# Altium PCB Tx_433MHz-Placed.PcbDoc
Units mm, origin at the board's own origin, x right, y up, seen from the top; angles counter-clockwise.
Board outline 100 x 50 mm, 4 copper layers (SIGNAL_1, SIGNAL_2, SIGNAL_3, SIGNAL_4), stack 1.58 mm thick; 34 components, 24 nets, 121 pads, 0 vias.
Unrouted connection lines stored in the file: 90.
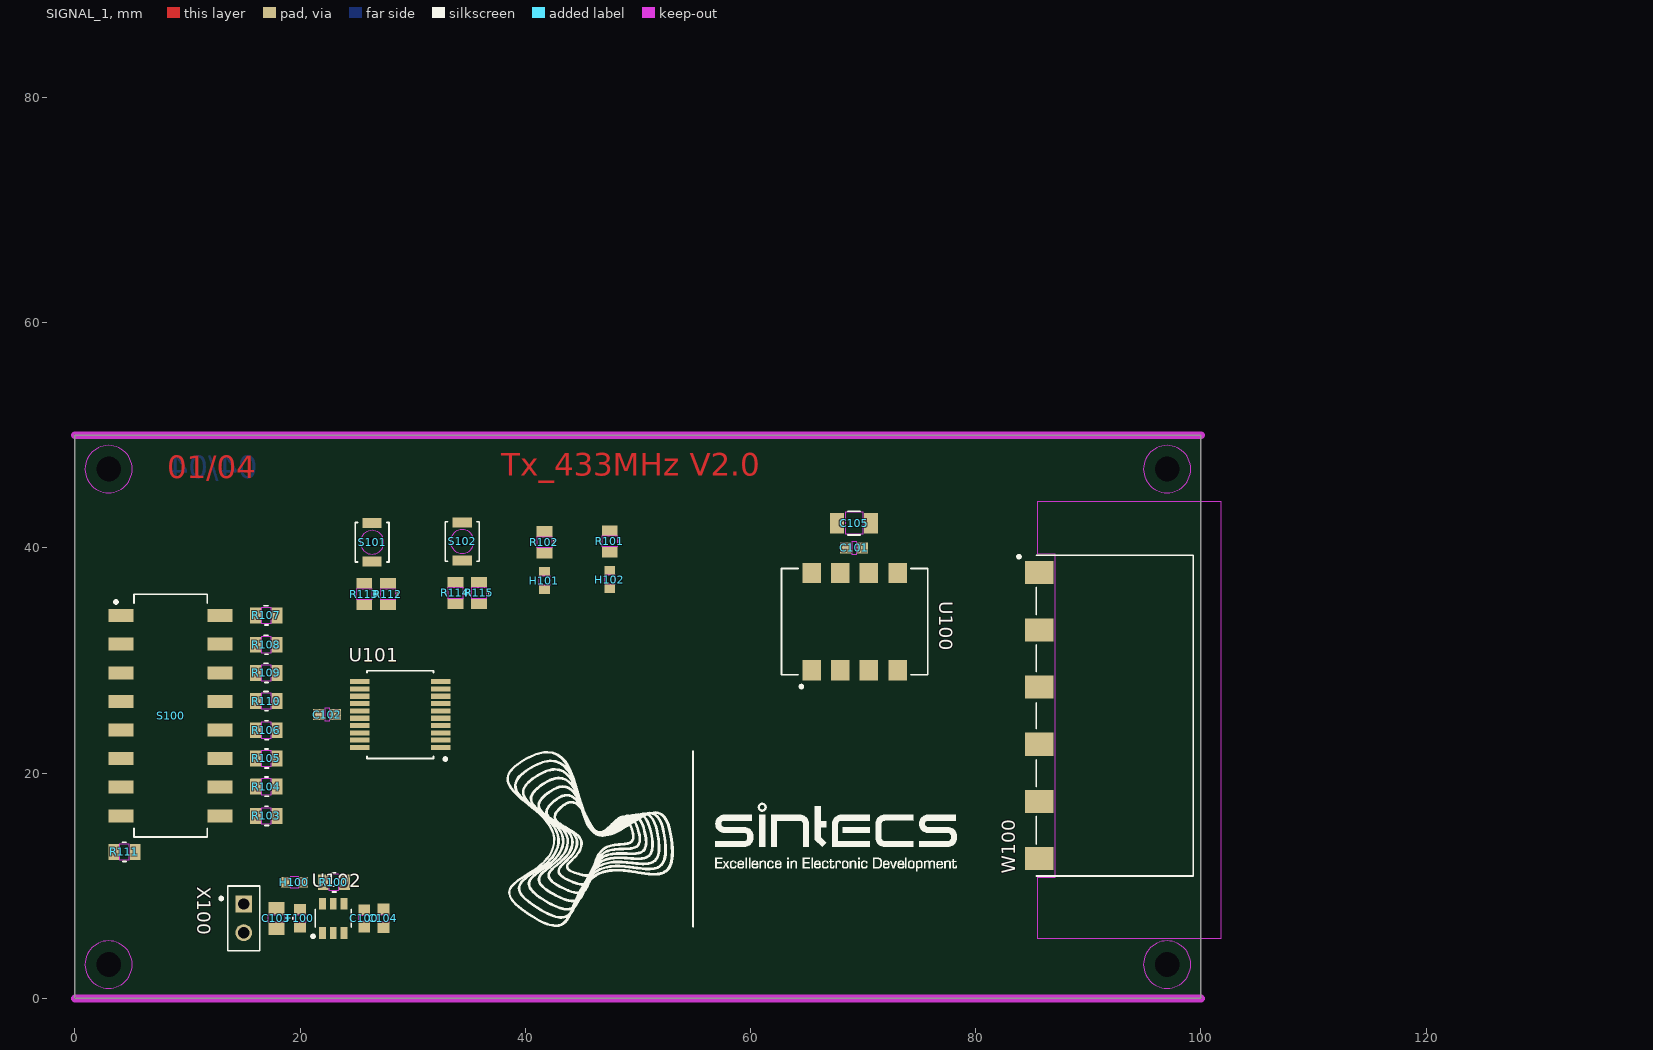
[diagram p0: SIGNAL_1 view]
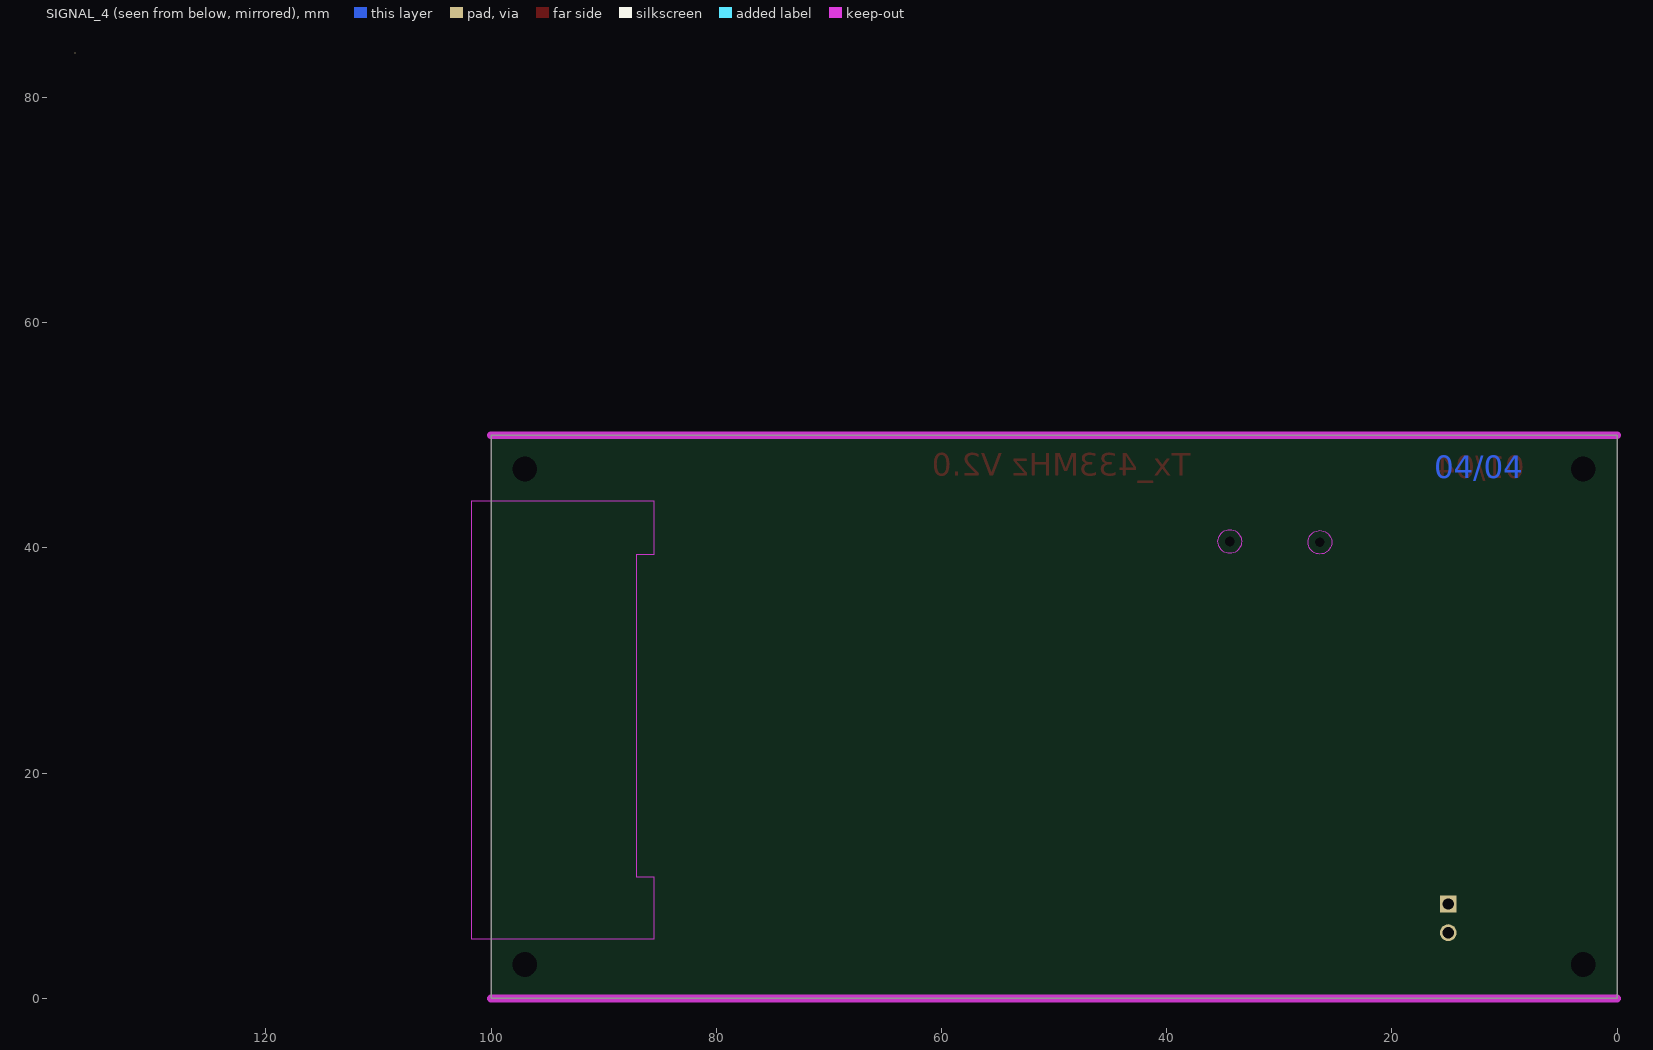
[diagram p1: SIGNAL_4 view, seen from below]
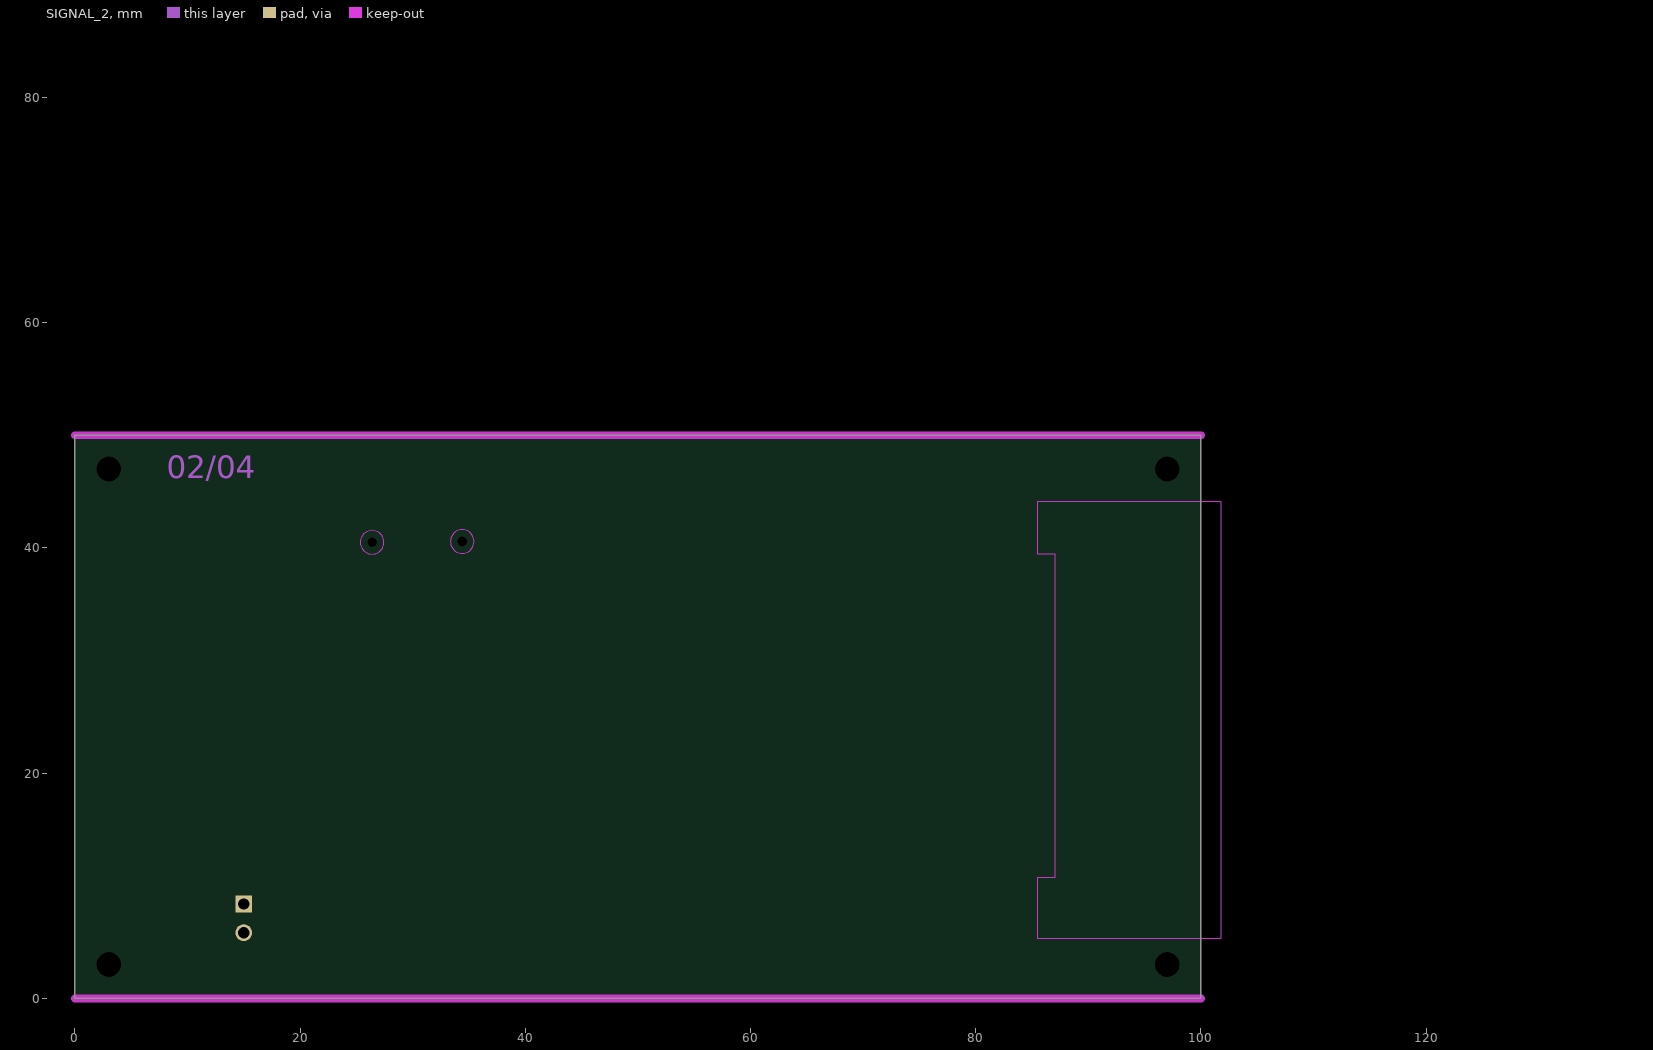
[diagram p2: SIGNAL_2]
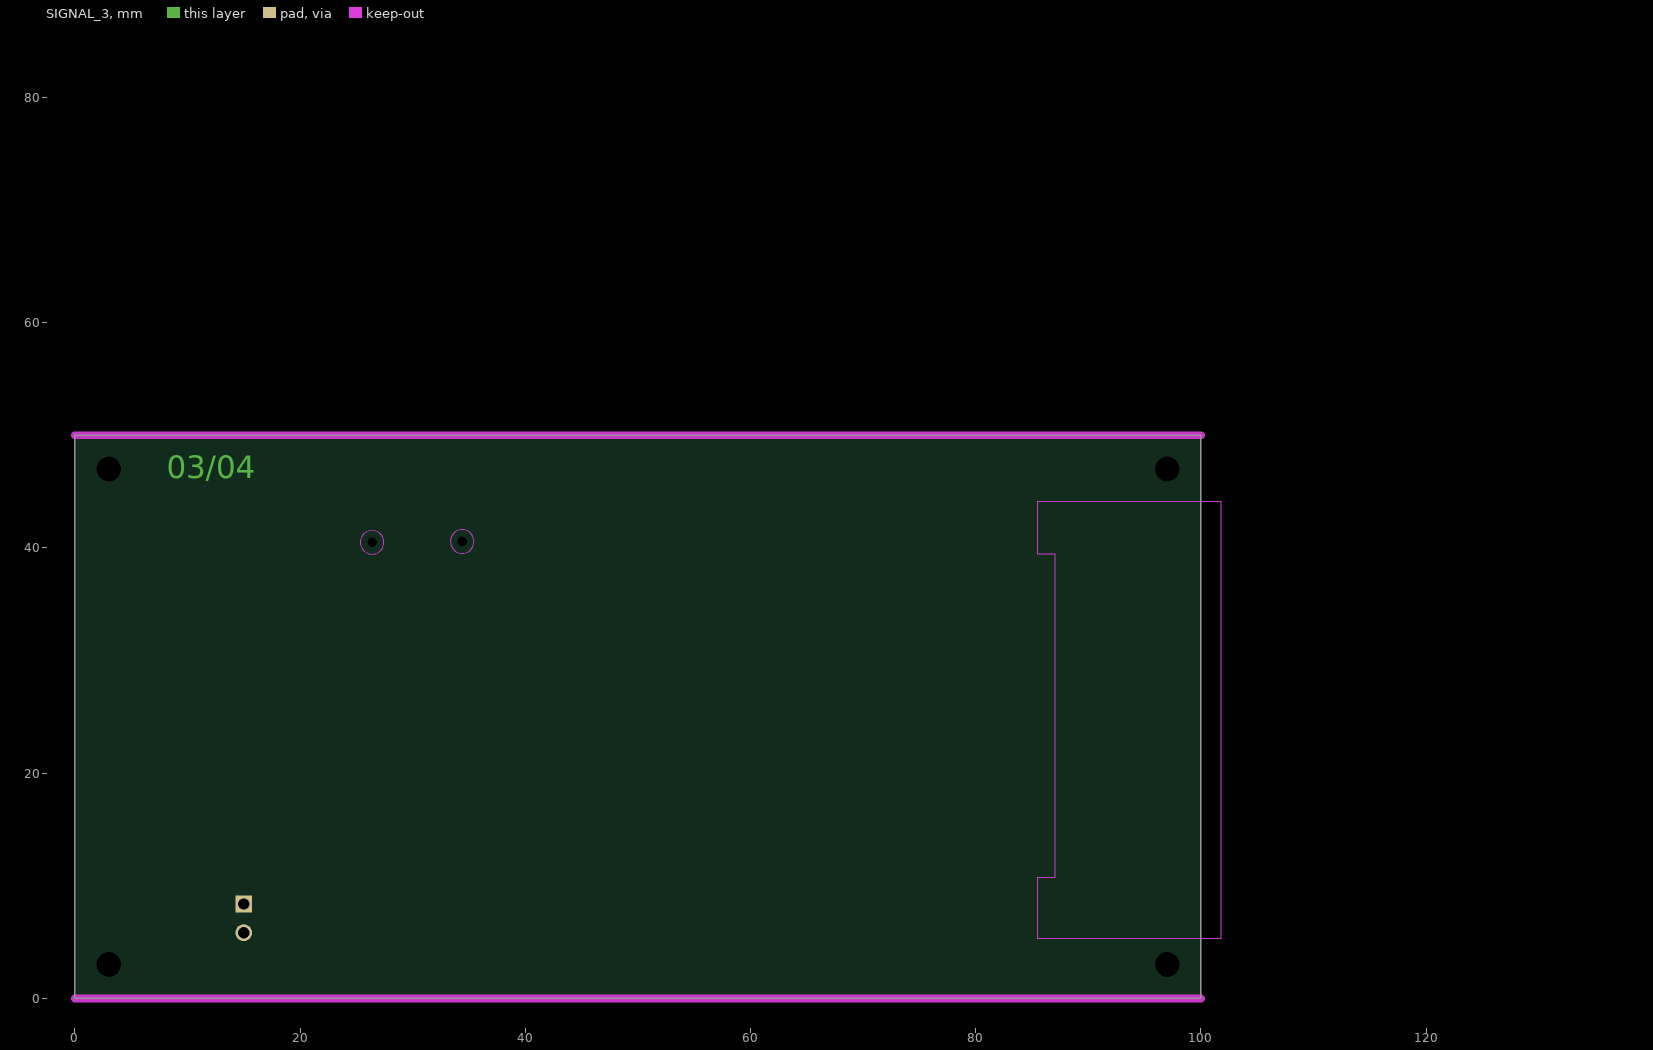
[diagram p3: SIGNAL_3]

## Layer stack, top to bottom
DIELECTRIC_1: solder mask 0.01, Dk 1
SIGNAL_1: signal copper 0.035
DIELECTRIC_3: prepreg 0.12, Dk 4.7
SIGNAL_2: signal copper 0.035
DIELECTRIC_5: prepreg 1.2, Dk 4.7
SIGNAL_3: signal copper 0.035
DIELECTRIC_7: prepreg 0.12, Dk 4.7
SIGNAL_4: signal copper 0.035
DIELECTRIC_9: solder mask 0.01, Dk 1

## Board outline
0,0 0,50 100,50 100,0

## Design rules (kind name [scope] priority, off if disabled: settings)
Clearance Clearance_50R [InNetClass('50R')] p1: gap=0.6 ignorepadtopadclearanceinfootprint=FALSE except(0.2: SMDPad-SMDPad)
Clearance [All] p2: gap=0.15 ignorepadtopadclearanceinfootprint=FALSE
ComponentClearance [All] p1: gap=0.1 collisioncheckmode=3 verticalgap=0.254 showdistances=FALSE
DiffPairsRouting [All] p1: maxlimit=0.254 minlimit=0.254 mostfreqgap=0.254 toplayer_minwidth=0.15 toplayer_maxwidth=0.3 toplayer_prefwidth=0.15 midlayer1_minwidth=0.15 midlayer1_maxwidth=0.3 midlayer1_prefwidth=0.15 midlayer2_minwidth=0.15 midlayer2_maxwidth=0.3 midlayer2_prefwidth=0.15 bottomlayer_minwidth=0.15 bottomlayer_maxwidth=0.3 bottomlayer_prefwidth=0.15 maxuncoupledlength=12.7
MinimumSolderMaskSliver [All] p1: minsoldermaskwidth=0.1
PolygonConnect [All] p1: thpad.connectstyle=Relief thpad.reliefconductorwidth=0.15 thpad.reliefentries=4 thpad.polygonreliefangle="90 Angle" thpad.airgapwidth=0.15 smdpad.connectstyle=Relief smdpad.reliefconductorwidth=0.15 smdpad.reliefentries=4 smdpad.polygonreliefangle="90 Angle" smdpad.airgapwidth=0.15 via.connectstyle=Direct via.reliefconductorwidth=0.127 via.reliefentries=2 via.polygonreliefangle="90 Angle" via.airgapwidth=0.152
RoutingVias [All] p1: holewidth=0.3 width=0.7 viastyle="Through Hole" minholewidth=0.3 minwidth=0.7 maxholewidth=0.3 maxwidth=0.7
SilkToSilkClearance [All] p1: silktosilkclearance=0.1
SolderMaskExpansion SolderMaskExpansion_Via [IsVia] p1: expansion=0.075 istentingtop=FALSE soldermaskfromhole=TRUE
SolderMaskExpansion [All] p2: expansion=0.1 istentingtop=FALSE
SupplyNets "Schematic Supply Nets_1" [InNet('GND_TX')] p1: voltage=0.000
SupplyNets "Schematic Supply Nets" [InNet('3V3_TX')] p2: voltage=0.000
UnRoutedNet [All] p1: checkbadconnections=TRUE
Width "Width for 50E_SE" [InNetClass('50R')] p1: maxlimit=0.2 minlimit=0.185 preferedwidth=0.2 toplayer_minwidth=0.2 bottomlayer_minwidth=0.2 impedanceprofiledriven=TRUE impedanceprofileid={877E34D1-77DC-4DEE-A0FB-207FE4FBDA97} impedanceprofilevalue=50.000000 minimp=50.000000 maximp=50.000000 favimp=50.000000
Width [All] p2: maxlimit=1 minlimit=0.15 preferedwidth=0.2
25 further rules are at their usual default settings.

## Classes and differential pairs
net class 50R: RF_TX
polygon class "\"(Inherited)\"": GND_RX_L02_P002

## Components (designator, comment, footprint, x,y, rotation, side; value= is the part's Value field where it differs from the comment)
C100 "C_0603_1608X90_GENERIC" CAPC1608X90N_0603_GENERIC 25.7,7.1 r90 top value=100nF
C101 "C_0603_1608X90_GENERIC" CAPC1608X90N_0603_GENERIC 69.2,40 r0 top value=100nF
C102 "C_0603_1608X90_GENERIC" CAPC1608X90N_0603_GENERIC 22.4,25.2 r180 top value=100nF
C103 "C_0805_2012X150_GENERIC" CAPC2012X150N_0805_GENERIC 17.9,7.1 r270 top value=1uF
C104 "CL10A226MP8NUNE" CAPC1608X105N 27.4,7.1 r90 top value=4.7uF
C105 "C_1206_3216X190_GENERIC" CAPC3216X190N_1206_GENERIC 69.2,42.2 r0 top value=10uF
F100 "0467XXXX" RESC1608X60N_0603_GENERIC 20,7.1 r270 top value=500mA
H100 "KP-1608SGC" LEDC1608X110N 19.5,10.3 r180 top
H101 "KP-1608SGC" LEDC1608X110N 41.7,37.1 r90 top
H102 "KP-1608SGC" LEDC1608X110N 47.5,37.175 r90 top
R100 "R_0805_2012X60_GENERIC" RESC2012X60N_0805_GENERIC 23,10.3 r180 top value=120R
R101 "R_0805_2012X60_GENERIC" RESC2012X60N_0805_GENERIC 47.5,40.575 r90 top value=120R
R102 "R_0805_2012X60_GENERIC" RESC2012X60N_0805_GENERIC 41.7,40.5 r90 top value=120R
R103 "R_0805_2012X60_GENERIC" RESC2012X60N_0805_GENERIC 17,16.2 r180 top value=100K
R104 "R_0805_2012X60_GENERIC" RESC2012X60N_0805_GENERIC 17,18.8 r180 top value=100K
R105 "R_0805_2012X60_GENERIC" RESC2012X60N_0805_GENERIC 17,21.3 r180 top value=100K
R106 "R_0805_2012X60_GENERIC" RESC2012X60N_0805_GENERIC 17,23.8 r180 top value=100K
R107 "R_0805_2012X60_GENERIC" RESC2012X60N_0805_GENERIC 17,34 r0 top value=100K
R108 "R_0805_2012X60_GENERIC" RESC2012X60N_0805_GENERIC 17,31.4 r0 top value=100K
R109 "R_0805_2012X60_GENERIC" RESC2012X60N_0805_GENERIC 17,28.9 r0 top value=100K
R110 "R_0805_2012X60_GENERIC" RESC2012X60N_0805_GENERIC 17,26.4 r0 top value=100K
R111 "R_0805_2012X60_GENERIC" RESC2012X60N_0805_GENERIC 4.4,13 r0 top value=1K
R112 "R_0805_2012X60_GENERIC" RESC2012X60N_0805_GENERIC 27.8,35.9 r90 top value=100K
R113 "R_0805_2012X60_GENERIC" RESC2012X60N_0805_GENERIC 25.7,35.9 r270 top value=1K
R114 "R_0805_2012X60_GENERIC" RESC2012X60N_0805_GENERIC 33.8,36 r270 top value=1K
R115 "R_0805_2012X60_GENERIC" RESC2012X60N_0805_GENERIC 35.9,36 r90 top value=100K
S100 "418121270808" WE_418121270808 8.5,25.1 r0 top
S101 "B3U_1000P_B" OMRON_B3U_1000P_B 26.4,40.5 r90 top
S102 "B3U_1000P_B" OMRON_B3U_1000P_B 34.402,40.57 r90 top
U100 "TXM-433-LR" LINX_TXM-433-LR 69.25,33.45 r90 top
U101 "LICAL-ENC-MS001" SOP65P780X200-20N 28.9,25.2 r180 top
U102 "MAX8881EU" SOT95P280X100-6N 22.95,7.1 r90 top
W100 "ANT-433-SP" LINX_ANT-433-SP 85.65,25.1 r270 top
X100 "M20_9770242" HARWIN_M20_9770242 15,7.1 r270 top

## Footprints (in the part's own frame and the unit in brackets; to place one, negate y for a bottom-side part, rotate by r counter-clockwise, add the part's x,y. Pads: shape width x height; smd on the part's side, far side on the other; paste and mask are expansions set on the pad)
CAPC1608X90N_0603_GENERIC [mm]
  rrect1% 1x1 smd paste-2539.97 mask-0.513: 1(-0.75,0) 2(0.75,0)
  SIGNAL_1 keep-out region: -0.22,-0.55 0.22,-0.55 0.22,0.55 -0.22,0.55
  body extent -1.5,-0.75 1.5,0.75, height 0.9
CAPC1608X105N [mm]
  rrect1% 1x1.05 smd paste-2539.97 mask-0.538: 1(-0.8,0) 2(0.8,0)
  SIGNAL_1 keep-out region: -0.3,-0.525 0.3,-0.525 0.3,0.525 -0.3,0.525
  body extent -1.55,-0.8 1.55,0.8, height 1.05
CAPC2012X150N_0805_GENERIC [mm]
  rrect1% 1.15x1.45 smd paste-2539.97 mask-0.738: 1(-0.9,0) 2(0.9,0)
  SIGNAL_1 keep-out region: -0.28,-0.78 0.28,-0.78 0.28,0.78 -0.28,0.78
  body extent -1.73,-1.05 1.73,1.05, height 1.5
CAPC3216X190N_1206_GENERIC [mm]
  rrect1% 1.25x1.8 smd paste-2539.97 mask-0.913: 1(-1.5,0) 2(1.5,0)
  SIGNAL_1 keep-out region: -0.8,-0.95 0.8,-0.95 0.8,0.95 -0.8,0.95
  silkscreen extent -0.55,-1.05 0.55,1.05, body extent -2.4,-1.15 2.4,1.15, height 1.9
HARWIN_M20_9770242 [mm]
  rrect1% 1.5x1.5 hole 1 paste-2539.97 mask-0.763: 1(-1.27,0)
  round 1.5 hole 1 paste-2539.97 mask-0.763: 2(1.27,0)
  silkscreen extent -2.87,-2.13 2.86,1.42, body extent -2.97,-1.52 2.96,1.52, height 8.38
LEDC1608X110N [mm]
  rrect1% 0.8x0.95 smd paste-2539.97 mask-0.488: 1(-0.8,0) 2(0.8,0)
  SIGNAL_1 keep-out region: -0.375,-0.5 0.375,-0.5 0.375,0.5 -0.375,0.5
  body extent -1.45,-0.75 1.45,0.75, height 0.65
LINX_ANT-433-SP [mm]
  rrect1% 2.05x2.55 smd paste-2539.97 mask-1.288: 1(-12.7,0) 2(-7.62,0) 3(-2.54,0) 4(2.54,0) 5(7.62,0) 6(12.7,0)
  SIGNAL_1 keep-out region: 14.35,-0.15 14.35,1.4 -14.35,1.4 -14.35,-0.15 -19.03,-0.15 -19.03,16.13 19.83,16.13 19.83,-0.15
  SIGNAL_2 keep-out region: 14.35,-0.15 14.35,1.4 -14.35,1.4 -14.35,-0.15 -19.03,-0.15 -19.03,16.13 19.83,16.13 19.83,-0.15
  SIGNAL_3 keep-out region: 14.35,-0.15 14.35,1.4 -14.35,1.4 -14.35,-0.15 -19.03,-0.15 -19.03,16.13 19.83,16.13 19.83,-0.15
  SIGNAL_4 keep-out region: 14.35,-0.15 14.35,1.4 -14.35,1.4 -14.35,-0.15 -19.03,-0.15 -19.03,16.13 19.83,16.13 19.83,-0.15
  silkscreen extent -14.25,-1.93 14.24,13.67, body extent -14.34,-1.55 14.34,13.77, height 1.5
LINX_TXM-433-LR [mm]
  rrect1% 1.8x1.65 smd paste-2539.97 mask-0.913: 1(-4.318,3.81) 2(-4.318,1.27) 3(-4.318,-1.27) 4(-4.318,-3.81) 5(4.318,-3.81) 6(4.318,-1.27) 7(4.318,1.27) 8(4.318,3.81)
  silkscreen extent -5.89,-6.5 4.72,6.5, body extent -5.5,-6.75 5.5,6.7, height 3.3
OMRON_B3U_1000P_B [mm]
  rrect1% 0.9x1.7 smd paste-2539.97 mask-0.863: 1(-1.7,0) 2(1.7,0)
  round 0 hole 0.85 unplated paste-2539.97 mask+0.925: ""(0,0)
  SIGNAL_1 keep-out region: 1.05,0 0.97,0.402 0.742,0.742 0.402,0.97 0,1.05 0,1.05 -0.402,0.97 -0.742,0.742 -0.97,0.402 -1.05,0 -1.05,0 -0.97,-0.402 -0.742,-0.742 -0.402,-0.97 0,-1.05 0,-1.05 0.402,-0.97 0.742,-0.742 0.97,-0.402 1.05,0
  SIGNAL_2 keep-out region: 1.05,0 0.97,0.402 0.742,0.742 0.402,0.97 0,1.05 0,1.05 -0.402,0.97 -0.742,0.742 -0.97,0.402 -1.05,0 -1.05,0 -0.97,-0.402 -0.742,-0.742 -0.402,-0.97 0,-1.05 0,-1.05 0.402,-0.97 0.742,-0.742 0.97,-0.402 1.05,0
  SIGNAL_3 keep-out region: 1.05,0 0.97,0.402 0.742,0.742 0.402,0.97 0,1.05 0,1.05 -0.402,0.97 -0.742,0.742 -0.97,0.402 -1.05,0 -1.05,0 -0.97,-0.402 -0.742,-0.742 -0.402,-0.97 0,-1.05 0,-1.05 0.402,-0.97 0.742,-0.742 0.97,-0.402 1.05,0
  SIGNAL_4 keep-out region: 1.05,0 0.97,0.402 0.742,0.742 0.402,0.97 0,1.05 0,1.05 -0.402,0.97 -0.742,0.742 -0.97,0.402 -1.05,0 -1.05,0 -0.97,-0.402 -0.742,-0.742 -0.402,-0.97 0,-1.05 0,-1.05 0.402,-0.97 0.742,-0.742 0.97,-0.402 1.05,0
  silkscreen extent -1.75,-1.5 1.75,1.5, body extent -2.4,-1.6 2.4,1.6, height 1.75
RESC1608X60N_0603_GENERIC [mm]
  rrect1% 0.95x1.05 smd paste-2539.97 mask-0.538: 1(-0.8,0) 2(0.8,0)
  SIGNAL_1 keep-out region: -0.3,-0.55 0.3,-0.55 0.3,0.55 -0.3,0.55
  silkscreen extent -0.08,-0.65 0.08,0.65, body extent -1.55,-0.8 1.55,0.8, height 0.6
RESC2012X60N_0805_GENERIC [mm]
  rrect1% 0.95x1.4 smd paste-2539.97 mask-0.713: 1(-0.95,0) 2(0.95,0)
  SIGNAL_1 keep-out region: -0.45,-0.7 0.45,-0.7 0.45,0.7 -0.45,0.7
  silkscreen extent -0.2,-0.85 0.15,0.85, body extent -1.7,-0.95 1.7,0.95, height 0.6
SOP65P780X200-20N [mm]
  rrect1% 1.75x0.45 smd paste-2539.97 mask-0.888: 1(-3.6,2.925) 2(-3.6,2.275) 3(-3.6,1.625) 4(-3.6,0.975) 5(-3.6,0.325) 6(-3.6,-0.325) 7(-3.6,-0.975) 8(-3.6,-1.625) 9(-3.6,-2.275) 10(-3.6,-2.925) 11(3.6,-2.925) 12(3.6,-2.275) 13(3.6,-1.625) 14(3.6,-0.975) 15(3.6,-0.325) 16(3.6,0.325) 17(3.6,0.975) 18(3.6,1.625) 19(3.6,2.275) 20(3.6,2.925)
  silkscreen extent -4.12,-3.9 2.95,4.08, body extent -4.75,-4 4.75,4, height 2
SOT95P280X100-6N [mm]
  rrect1% 1.05x0.6 smd paste-2539.97 mask-0.538: 1(-1.3,0.95) 2(-1.3,0) 3(-1.3,-0.95) 4(1.3,-0.95) 5(1.3,0) 6(1.3,0.95)
  silkscreen extent -1.72,-1.6 0.8,1.92, body extent -2.1,-1.7 2.1,1.7, height 1
WE_418121270808 [mm]
  rrect1% 2.2x1.15 smd paste-2539.97 mask-1.113: 1(-4.4,8.89) 2(-4.4,6.35) 3(-4.4,3.81) 4(-4.4,1.27) 5(-4.4,-1.27) 6(-4.4,-3.81) 7(-4.4,-6.35) 8(-4.4,-8.89) 9(4.4,-8.89) 10(4.4,-6.35) 11(4.4,-3.81) 12(4.4,-1.27) 13(4.4,1.27) 14(4.4,3.81) 15(4.4,6.35) 16(4.4,8.89)
  silkscreen extent -4.97,-10.78 3.25,10.78, body extent -5.75,-10.9 5.75,10.9, height 4.32

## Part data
C100 C101 C102: "100nF 25V 10%", Capacitance=100000, Dielectric=X7R, Manufacturer=MURATA, MPN=GRM188R71E104KA01D, Package=0603, Part Name="Ceramic chip capacitor 0603-1608x90, generic", Tolerance=10, Voltage=25V
C103: "1µF 25V 10%", Capacitance=1000000, Dielectric=X7R, Manufacturer=AVX, MPN=08053C105K4Z2A, Package=0805, Part Name="Ceramic chip capacitor 0805-2012x150, generic", Tolerance=10, Voltage=25V
C104: "4.7uF 25V 10%", Alternate Manufacturer=SAMSUNG, Alternate MPN=CL10A475KA8NQNC, Capacitance=4700000, Dielectric=X5R, Manufacturer=AVX, MPN=06033D475KAT2A, Package=0603, Part Name="CAP 22uF 10V 0603 X5R", Tolerance=10, Voltage=25V
C105: "10uF 25V 10%", Capacitance=10000000, Dielectric=X7R, Manufacturer=AVX, Max Temp=+125, Min Temp=-55, MPN=12063C106KAT2A, Package=1206, Part Name="Cheramic chip capacitor 1206-3216x190, generic", Tolerance=10, Voltage=25V
F100: "Thin film 0603 fuse very fast acting", Current=0.5, Manufacturer=LITTELFUSE, Max Temp=+90, Min Temp=-55, MPN=0467.500NRHF, Package=0603, Part Name="Thin film 0603 very fast acting", Voltage=32V
H100 H101 H102: "LED Green", Current=20mA, Manufacturer=KINGBRIGHT, MPN=APT-1608SGC, Package=0603, Part Name="SMD LED lamp, Green"
R100 R101 R102: "0.125W 5% 120R 50V", Manufacturer=YAGEO, MPN=RC0805JR-07120RL, Package=0805, Part Name="resistor_0805-2012x60 generic", Tolerance=5%
R103 R104 R105 R106 R107 R108 R109 R110 R112 R115: "0.125W 5% 100K 50V", Manufacturer=YAGEO, MPN=RC0805JR-07100KL, Package=0805, Part Name="resistor_0805-2012x60 generic", Tolerance=5%
R111 R113 R114: "Resistor_1K_1%_0805", Manufacturer=MULTICOMP, MPN=MCPWR05FTEW1001, Package=0805, Part Name="resistor_0805-2012x60 generic", Tolerance=1%
S100: "Dip Switch SPST 8 Position Surface Mount Slide (Standard) Actuator 25mA 24VDC", Current=25mA, Manufacturer="WURTH ELEKTRONIK", Max Temp=85, Min Temp=-40, Part Name="Dip Switch SPST 8 Position Surface Mount", Voltage=24
S101 S102: "Ultra-small Tactile Switch", Manufacturer=OMRON, Max Temp=0, MPN=B3U-1000P-B
U100: "LR Series Transmitter, Low Voltage, Low Power", Manufacturer="Linx Technologies", Max Temp=85, Min Temp=-40, Package=custom
U101: "MS Series Remote Controler Encoder, Low Voltage, Low Power", Manufacturer="LINX TECHNOLOGIES", Max Temp=85, Min Temp=-40, Package=SOP-20
U102: "Low Dropout Linear Regulator with enable and power good, 3.3V, 6 pin SOT23", Manufacturer=MAXIM, Max Temp=85, Min Temp=-40, MPN=MAX8881EUT33+T, Output Current=0.20A, Package=SOT23-6, Part Name="Low Dropout Linear Regulator, 6 pin SOT23"
W100: "433MHz 50 Ohm Antenna module", Manufacturer="Linx Technologies", Max Temp=130, Min Temp=-40, Package=custom
X100: "1x2 pin 2.54 mm pitch vertical header", Manufacturer=HARWIN, MPN=M20-9770242, Package=header, Part Name=STD_HEADER_1x2_2.54_THT

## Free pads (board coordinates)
  round 0 hole 2.2 unplated paste-2539.97 mask+1.6: ""(3,3) ""(3,47) ""(97,3) ""(97,47)
  round 0.025 smd far side paste-2539.97 mask-127: ""(136.95,83.95)

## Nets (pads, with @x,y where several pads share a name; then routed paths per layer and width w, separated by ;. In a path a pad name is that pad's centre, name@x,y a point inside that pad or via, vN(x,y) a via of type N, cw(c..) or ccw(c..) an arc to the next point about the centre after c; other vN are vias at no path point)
3V3_TX: C100.1 C101.1 C102.1 C104.1 C105.1 R100.1 R111.2 S101.2 S102.2 U100.4 U100.7 U101.15 U101.16 U102.3 U102.4
GND_TX: C100.2 C101.2 C102.2 C103.2 C104.2 C105.2 H100.2 R101.2 R102.2 R103.1 R104.1 R105.1 R106.1 R107.2 R108.2 R109.2 R110.2 R112.1 R115.1 U100.1 U100.3 U100.6 U101.3 U101.4 U101.5 U101.6 U101.7 U102.2 W100.2 W100.3 W100.4 W100.5 W100.6 X100.2
NetC103_1: C103.1 F100.1 X100.1
NetF100_2: F100.2 U102.1 U102.5
NetH100_1: H100.1 R100.2 U102.6
NetH101_1: H101.1 U100.8 U101.8
NetH101_2: H101.2 R102.1
NetH102_1: H102.1 U101.10
NetH102_2: H102.2 R101.1
NetR103_2: R103.2 S100.9 U101.20
NetR104_2: R104.2 S100.10 U101.19
NetR105_2: R105.2 S100.11 U101.18
NetR106_2: R106.2 S100.12 U101.17
NetR107_1: R107.1 S100.16 U101.1
NetR108_1: R108.1 S100.15 U101.2
NetR109_1: R109.1 S100.14 U101.13
NetR110_1: R110.1 S100.13 U101.14
NetR111_1: R111.1 S100.1 S100.2 S100.3 S100.4 S100.5 S100.6 S100.7 S100.8
NetR112_2: R112.2 R113.1 S101.1
NetR113_2: R113.2 U101.12
NetR114_1: R114.1 R115.2 S102.1
NetR114_2: R114.2 U101.11
NetU100_2: U100.2 U101.9
RF_TX: U100.5 W100.1
pads on no net: S101. S102.

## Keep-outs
SIGNAL_1:
  region: 5.1,3 ccw(c3,3) 3,5.1 ccw(c3,3) 0.9,3 ccw(c3,3) 3,0.9 ccw(c3,3)
  region: 99.1,3 ccw(c97,3) 97,5.1 ccw(c97,3) 94.9,3 ccw(c97,3) 97,0.9 ccw(c97,3)
  region: 99.1,47 ccw(c97,47) 97,49.1 ccw(c97,47) 94.9,47 ccw(c97,47) 97,44.9 ccw(c97,47)
  region: 5.1,47 ccw(c3,47) 3,49.1 ccw(c3,47) 0.9,47 ccw(c3,47) 3,44.9 ccw(c3,47)
Keep-Out Layer:
  lines w0.7: 0,0 100,0 ; 0,50 100,50

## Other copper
SIGNAL_1:
  pour cut-out: 5.1,3 ccw(c3,3) 3,5.1 ccw(c3,3) 0.9,3 ccw(c3,3) 3,0.9 ccw(c3,3)
  pour cut-out: 99.1,3 ccw(c97,3) 97,5.1 ccw(c97,3) 94.9,3 ccw(c97,3) 97,0.9 ccw(c97,3)
  pour cut-out: 99.1,47 ccw(c97,47) 97,49.1 ccw(c97,47) 94.9,47 ccw(c97,47) 97,44.9 ccw(c97,47)
  pour cut-out: 5.1,47 ccw(c3,47) 3,49.1 ccw(c3,47) 0.9,47 ccw(c3,47) 3,44.9 ccw(c3,47)
  text "Tx_433MHz V2.0" at 37.866,46.425 h2
  text "01/04" at 8.186,46.175 h2
  text "Layer 01/04 Top" at 33.324,-23.065 h2
SIGNAL_2:
  text "02/04" at 8.156,46.175 h2
  text "Layer 02/04" at 33.324,-23.065 h2
SIGNAL_3:
  text "03/04" at 8.156,46.175 h2
  text "Layer 03/04" at 33.324,-23.065 h2
SIGNAL_4:
  text "04/04" at 16.264,46.175 h2
  text "Layer 04/04 Bottom" at 69.073,-23.065 h2

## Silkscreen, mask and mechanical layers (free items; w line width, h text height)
Top Overlay:
  drawing of 94 lines, arcs and shapes, not listed
  text "SILKSCREEN TOP" at 66.497,-23.235 h2
DIELECTRIC_1:
  text "SOLDERMASK TOP" at 33.334,-23.005 h2
DIELECTRIC_9:
  text "SOLDERMASK BOTTOM" at 33.344,-23.005 h2
Top Assembly:
  text "U100" at 67.25,32.85 h1
  text "U101" at 27.35,25.05 h1
  text "W100" at 90.5,24.7 h1
  text "U102" at 22.3,7 h0.5
  text "X100" at 15.35,5.5 h1 r90
  text "Assembly Drawing Top" at 33.604,-23.29 h2
Default User Layer:
  lines w0.025: 1,1 1,49 ; 1,1 85,1 ; 1,1 1,49 ; 1,1 85,1 ; 1,49 85,49 ; 1,49 85,49 ; 85,1 85,49 ; 85,1 85,49
VSCORE_DETAIL:
  text "VSCORE DETAIL" at 33.334,-23.005 h2
Panel Dimension:
  circle w0.2: c3,3 r1.1
  circle w0.2: c3,47 r1.1
  circle w0.2: c97,47 r1.1
  circle w0.2: c97,3 r1.1
  text "Panel Drawing" at 33.864,-23.295 h2
Single Board Dimensions:
  circle w0.2: c97,3 r1.1
  circle w0.2: c97,47 r1.1
  circle w0.2: c3,47 r1.1
  circle w0.2: c3,3 r1.1
  lines w0.05: 0,0 0,50 ; 0,0 50,0 100,0 ; 0,0 0,50 ; 0,50 100,50 ; 0,50 100,50 ; 0,50 100,50 ; 100,0 100,50 ; 100,0 100,50
  text "Single Board Dimensions" at 33.334,-23.005 h2
TitleBlock_Mirrored:
  drawing of 102 lines, arcs and shapes, not listed
  text "PROJECT:" at 76.049,-13.849 h0.76
  text "TX & RX 433MHZ UT Scintilla Workshop" at 68.987,-15.551 h2
  text "DRAWN BY:" at 76.049,-17.659 h0.76
  text "Lesley Snijder/Henk Mengerink" at 69.191,-19.281 h2
  text "LAYER:" at 76.049,-21.469 h0.76
  text "DATE:" at 16.613,-25.279 h0.76
  text "REV:" at 26.519,-25.279 h0.76
  text "DWG NO:" at 76.049,-25.279 h0.76
  text "30 Apr2021" at 12.549,-27.041 h2
  text "2.0" at 23.217,-27.041 h2
  text "THE INFORMATION HEREIN IS PROPRIETARY TO YOUR DESIGN COMPANY" at 111.709,-27.628 h0.64
TittleBlock:
  drawing of 102 lines, arcs and shapes, not listed
  text "PROJECT:" at 26.889,-13.869 h0.76
  text "TX & RX 433MHZ UT Scintilla Workshop" at 33.747,-15.531 h2
  text "DRAWN BY:" at 26.889,-17.679 h0.76
  text "Lesley Snijder/Henk Mengerink" at 33.747,-19.301 h2
  text "LAYER:" at 26.889,-21.489 h0.76
  text "DWG NO:" at 26.889,-25.299 h0.76
  text "REV:" at 76.419,-25.299 h0.76
  text "DATE:" at 86.325,-25.299 h0.76
  text "2.0" at 79.721,-27.061 h2
  text "30 Apr 2021" at 90.389,-27.061 h2
  text "THE INFORMATION HEREIN IS PROPRIETARY TO YOUR DESIGN COMPANY" at -8.771,-27.648 h0.64
Drill Drawing:
  lines w0.15: -22.95,-45.95 134.55,-45.95 ; -22.95,-39.95 134.55,-39.95 ; -22.95,-62.45 -22.95,-30.95 134.55,-30.95 134.55,-62.45 -22.95,-62.45
  text "E" at 3,96 h2
  text "E" at 97,96 h2
  text "A" at 66.42,91.24 h2
  text "A" at 71.68,91.24 h2
  text "A" at 43.09,90.65 h2
  text "A" at 56.5,90.65 h2
  text "A" at 31,88.55 h2
  text "A" at 6.98,88.49 h2
  text "D" at 43.1,88 h2
  text "D" at 56.5,88 h2
  text "A" at 49.85,87.74 h2
  text "A" at 38.54,86.13 h2
  text "A" at 18.66,85.93 h2
  text "A" at 78.64,85 h2
  text "A" at 82.3,84.67 h2
  text "A" at 41.17,84.05 h2
  text "A" at 54.57,84.05 h2
  text "A" at 83.76,81.72 h2
  text "A" at 78.92,80.83 h2
  text "A" at 58.77,79.72 h2
  text "A" at 51.12,78.4 h2
  text "A" at 54.98,78.4 h2
  text "A" at 65.43,76.73 h2
  text "A" at 70.52,76.73 h2
  text "A" at 73.05,76.73 h2
  text "A" at 6.89,76.65 h2
  text "A" at 83.76,76.64 h2
  text "A" at 51.12,75.85 h2
  text "A" at 54.98,75.85 h2
  text "A" at 68.6,75.09 h2
  text "A" at 30.84,74.25 h2
  text "A" at 56.5,74.18 h2
  text "A" at 51.12,73.3 h2
  text "A" at 79.23,73.15 h2
  text "A" at 83.76,71.56 h2
  text "A" at 51.12,70.8 h2
  text "A" at 79.23,70.6 h2
  text "A" at 65.64,70.55 h2
  text "A" at 68.69,69.57 h2
  text "A" at 54.9,69.55 h2
  text "A" at 18.54,68.46 h2
  text "A" at 57.4,68.46 h2
  text "A" at 65.65,68.25 h2
  text "A" at 51.12,68.2 h2
  text "A" at 69.01,67.28 h2
  text "A" at 83.76,66.48 h2
  text "A" at 69.01,65.96 h2
  text "A" at 51.12,65.7 h2
  text "A" at 70.96,64.65 h2
  text "A" at 79.05,64.65 h2
  text "A" at 69.7,64.39 h2
  text "A" at 51.12,63.15 h2
  text "A" at 6.78,62.23 h2
  text "C" at 60.23,61.67 h2
  text "A" at 83.76,61.4 h2
  text "A" at 51.12,60.6 h2
  text "A" at 64.84,60.6 h2
  text "A" at 30.67,59.95 h2
  text "C" at 60.23,59.13 h2
  text "A" at 64.85,59.1 h2
  text "A" at 78.85,57.44 h2
  text "E" at 3,52 h2
  text "E" at 97,52 h2
  text "E" at 3,46 h2
  text "E" at 97,46 h2
  text "A" at 4.63,41.86 h2
  text "A" at 29.48,41.21 h2
  text "A" at 66.43,40.71 h2
  text "C" at 45.53,40.68 h2
  text "C" at 48.07,40.68 h2
  text "A" at 53.83,40.7 h2
  text "B" at 3.055,38.58 h2
  text "B" at 18.295,38.58 h2
  text "A" at 47.53,38 h2
  text "A" at 34.53,37.67 h2
  text "A" at 50.78,36.1 h2
  text "A" at 46.55,36.06 h2
  text "B" at 3.055,36.04 h2
  text "B" at 18.295,36.04 h2
  text "A" at 46.56,34.91 h2
  text "A" at 77.44,34.69 h2
  text "A" at 82.12,34.69 h2
  text "A" at 50.78,34.2 h2
  text "A" at 74.65,34.16 h2
  text "A" at 34.53,33.87 h2
  text "B" at 3.055,33.5 h2
  text "B" at 18.295,33.5 h2
  text "A" at 39.37,32.92 h2
  text "A" at 42.26,32.6 h2
  text "A" at 50.79,31.77 h2
  text "A" at 83.11,31.62 h2
  text "A" at 39.37,31.02 h2
  text "B" at 3.055,30.96 h2
  text "B" at 18.295,30.96 h2
  text "A" at 51.5,29.2 h2
  text "A" at 78.52,28.46 h2
  text "B" at 3.055,28.42 h2
  text "B" at 18.295,28.42 h2
  text "A" at 37.98,28.32 h2
  text "A" at 26.55,26.7 h2
  text "A" at 83.11,26.54 h2
  text "A" at 30.1,26.47 h2
  text "A" at 51.5,26.21 h2
  text "A" at 25.5,26 h2
  text "A" at 14.55,24.94 h2
  text "C" at 42,23.78 h2
  text "A" at 30.78,23.09 h2
  text "A" at 37.97,23.1 h2
  text "A" at 51.12,22.25 h2
  text "B" at 2.905,21.78 h2
  text "B" at 18.145,21.78 h2
  text "A" at 83.11,21.46 h2
  text "C" at 42,21.24 h2
  text "A" at 34.53,19.89 h2
  text "B" at 2.905,19.24 h2
  text "B" at 18.145,19.24 h2
  text "C" at 42,18.7 h2
  text "A" at 48.38,18.56 h2
  text "B" at 2.905,16.7 h2
  text "B" at 18.145,16.7 h2
  text "A" at 48.38,16.66 h2
  text "A" at 83.11,16.38 h2
  text "C" at 42,16.16 h2
  text "A" at 34.53,16.08 h2
  text "A" at 63.03,15.82 h2
  text "A" at 39.39,15.15 h2
  text "A" at 60.27,14.54 h2
  text "B" at 2.905,14.16 h2
  text "B" at 18.145,14.16 h2
  text "A" at 78.41,14.04 h2
  text "A" at 66.43,13.85 h2
  text "C" at 42,13.62 h2
  text "A" at 39.37,13.24 h2
  text "A" at 60.24,12.92 h2
  text "A" at 49.35,12.9 h2
  text "A" at 51.85,11.73 h2
  text "B" at 2.905,11.62 h2
  text "B" at 18.145,11.62 h2
  text "A" at 63.25,11.59 h2
  text "A" at 83.11,11.3 h2
  text "C" at 42,11.08 h2
  text "A" at 63.39,10.63 h2
  text "A" at 39.19,9.84 h2
  text "A" at 63.39,9.31 h2
  text "A" at 66.49,8.88 h2
  text "A" at 58.79,8.73 h2
  text "A" at 26,8.7 h2
  text "A" at 30.05,8.7 h2
  text "C" at 42,8.54 h2
  text "A" at 37.1,7.14 h2
  text "A" at 52.5,6.8 h2
  text "D" at 55.15,6.8 h2
  text "A" at 13.66,6.75 h2
  text "C" at 42,6 h2
  text "A" at 30.94,5.5 h2
  text "E" at 3,2 h2
  text "E" at 97,2 h2
  text "Through Holes" at 47.75,-34.7 h1.5
  text "All Drills (unless specified) +/- 0.1000 (MM)" at 25.675,-37.7 h1.5
  text "Symbol" at -19.208,-43.7 h1.5
  text "Diameter" at 1.834,-43.7 h1.5
  text "Tolerance" at 29.561,-43.7 h1.5
  text "Plated" at 52.798,-43.7 h1.5
  text "HoleName" at 85.805,-43.7 h1.5
  text "Quantity" at 120.337,-43.7 h1.5
  text "A" at -15.45,-48.2 h1.5
  text "0.3000" at 3.379,-48.2 h1.5
  text "+/- 0.1000" at 29.132,-48.2 h1.5
  text "Yes" at 55.01,-48.2 h1.5
  text "Rnd 0.30 +/-Tol 0.10" at 77.714,-48.2 h1.5
  text "114" at 124.046,-48.2 h1.5
  text "B" at -15.45,-51.2 h1.5
  text "0.9000" at 3.379,-51.2 h1.5
  text "+/- 0.1000" at 29.132,-51.2 h1.5
  text "Yes" at 55.01,-51.2 h1.5
  text "Rnd 0.90 +/-Tol 0.10" at 77.714,-51.2 h1.5
  text "20" at 124.766,-51.2 h1.5
  text "C" at -15.45,-54.2 h1.5
  text "1.0000" at 3.402,-54.2 h1.5
  text "+/- 0.1000" at 29.132,-54.2 h1.5
  text "Yes" at 55.01,-54.2 h1.5
  text "Rnd 1.00 +/-Tol 0.10" at 77.74,-54.2 h1.5
  text "12" at 124.78,-54.2 h1.5
  text "D" at -15.45,-57.2 h1.5
  text "0.8500" at 3.385,-57.2 h1.5
  text "+/- 0.1000" at 29.132,-57.2 h1.5
  text "No" at 55.767,-57.2 h1.5
  text "Rnd 0.85 +/-Tol 0.10 Non-Plated" at 69.797,-57.2 h1.5
  text "3" at 125.55,-57.2 h1.5
  text "E" at -15.45,-60.2 h1.5
  text "2.2000" at 3.379,-60.2 h1.5
  text "+/- 0.1000" at 29.132,-60.2 h1.5
  text "No" at 55.767,-60.2 h1.5
  text "Rnd 2.20 +/-Tol 0.10 Non-Plated" at 69.79,-60.2 h1.5
  text "8" at 125.55,-60.2 h1.5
